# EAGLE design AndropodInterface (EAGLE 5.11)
AVAILABLE_QUANTITY: 27023; CREATE_DATE: 28.12.10; DATASHEET: http://www.farnell.com/cad/44942.pdf; DISTRIBUTOR: farnell.com; EDIT_DATE: 22.09.11; MANUFACTURER: MOLEX; MAUFACTURER: AVAGO; MINIMUM_QUANTITY: 1; ORDER_NO: 1568026; PARTS_PER_PACKAGE: 1; PART_NO: 47346-0001; PRICE: 1.21; PRICES: 1-0:1.21|25-0:1|50-0:0.834|100-0:0.725|500--1:0.629|; QUANTITY_MULTIPLIER: 1; TITLE: Andropod Interface
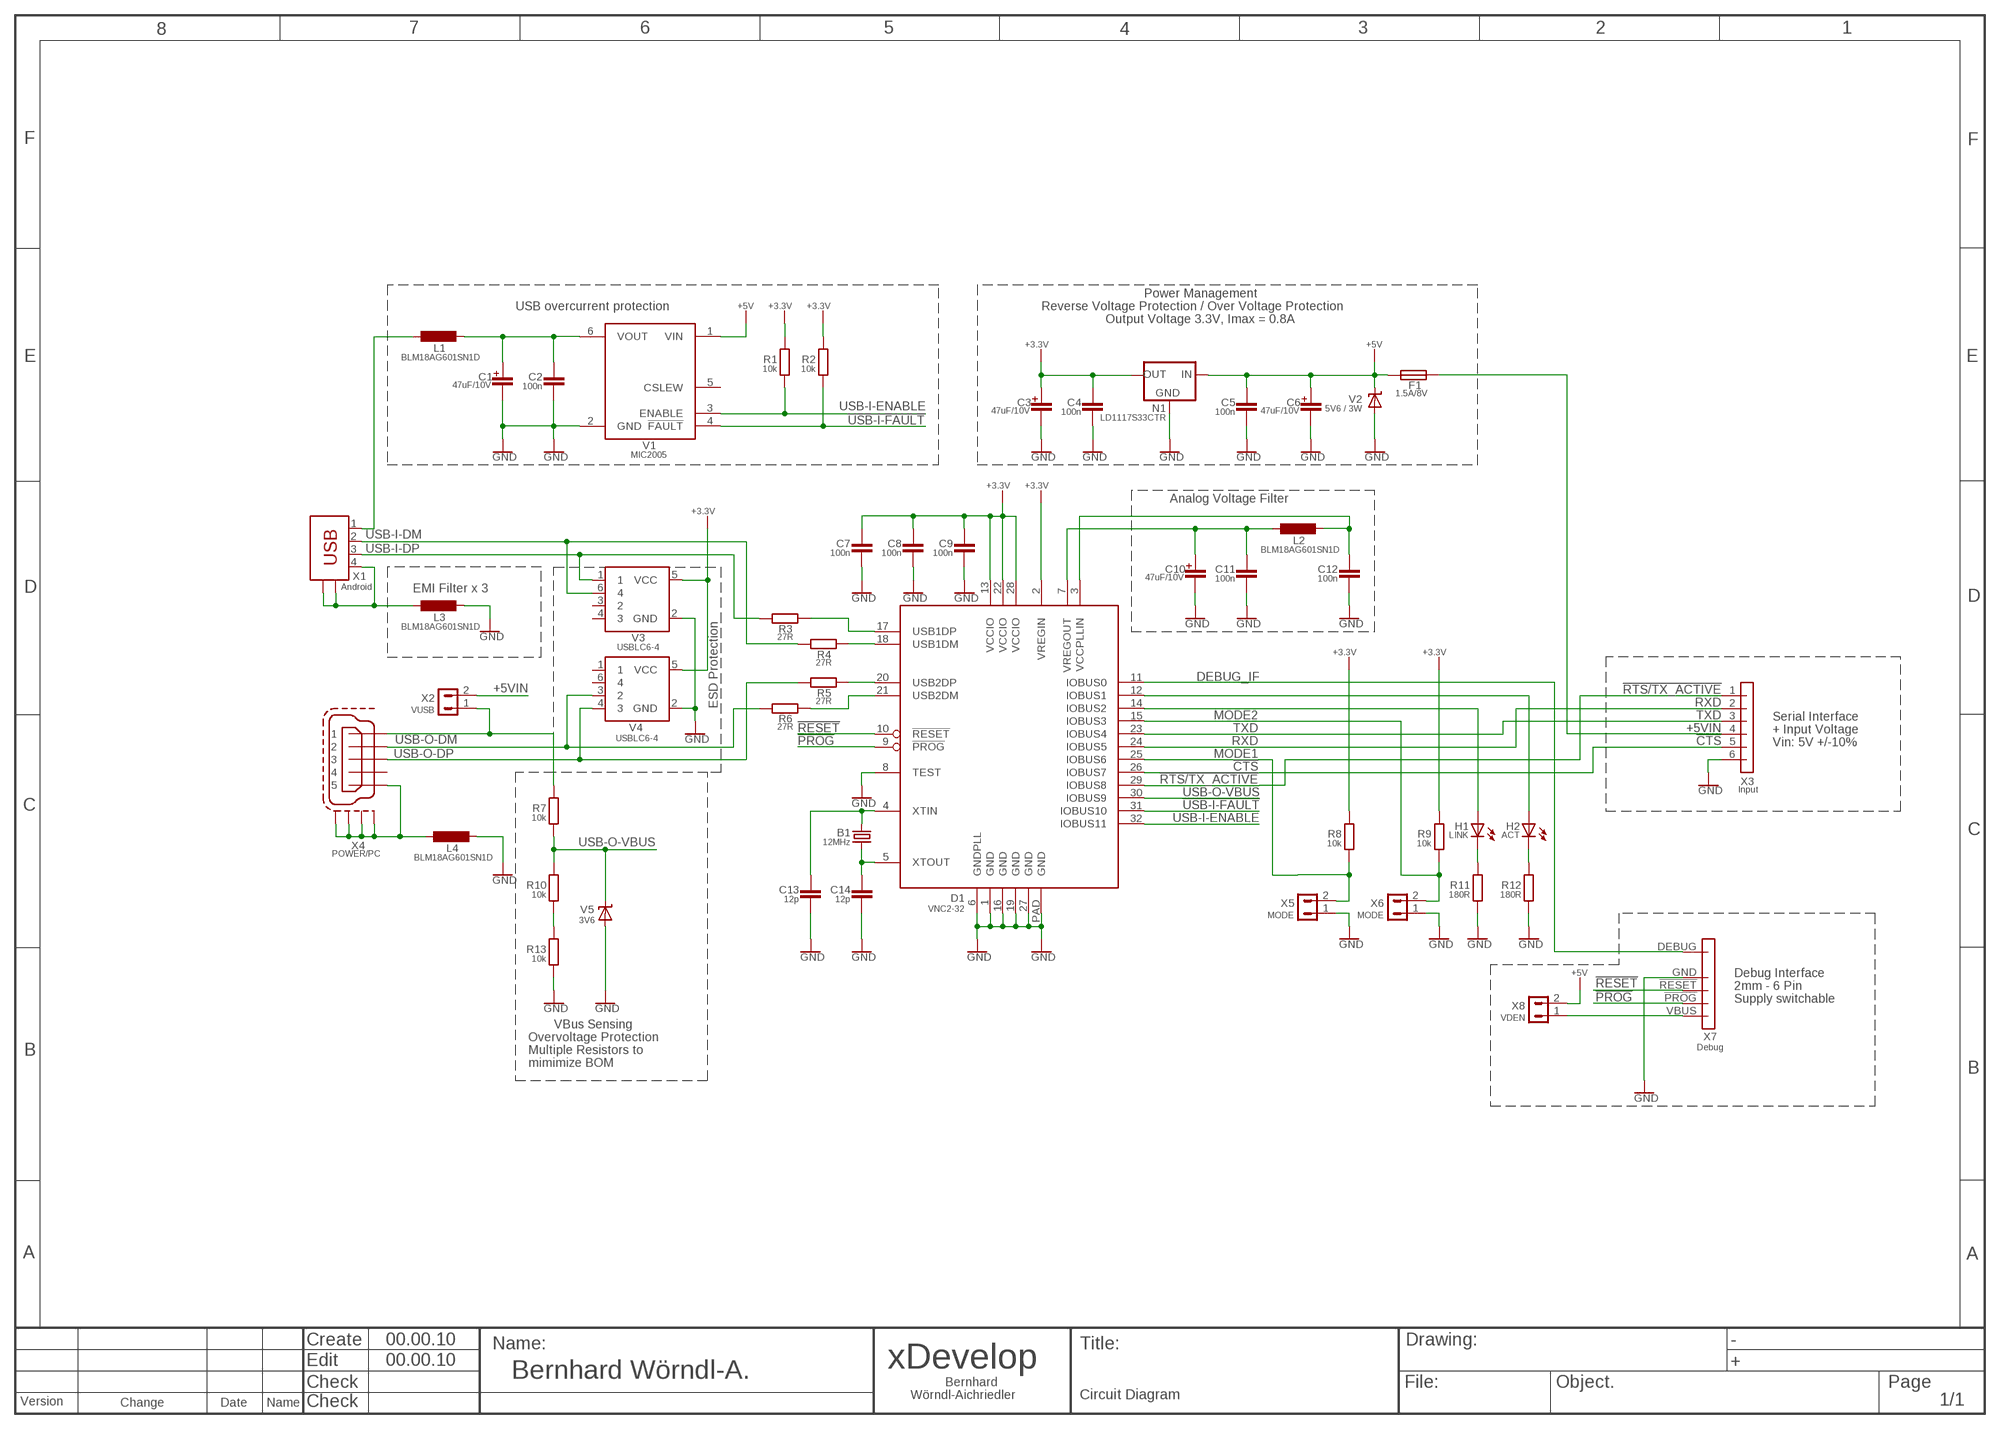
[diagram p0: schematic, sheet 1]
U$3 (XDEVELOP-A3): CREATE_DATE: 00.00.10; EDIT_DATE: 00.00.10; SUBTITLE: Circuit Diagram; USERNAME: Bernhard Wörndl-A.

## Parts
B1  12MHz  CRYSTAL5X3.2  [CRYSTAL-3.2X5.0MM]
C1  47uF/10V  CPOL-EUB/3528-21R  [B/3528-21R]
C2  100n  C-EUC0603  [C0603]
C3  47uF/10V  CPOL-EUB/3528-21R  [B/3528-21R]
C4  100n  C-EUC0603  [C0603]
C5  100n  C-EUC0603  [C0603]
C6  47uF/10V  CPOL-EUB/3528-21R  [B/3528-21R]
C7  100n  C-EUC0603  [C0603]
C8  100n  C-EUC0603  [C0603]
C9  100n  C-EUC0603  [C0603]
C10  47uF/10V  CPOL-EUB/3528-21R  [B/3528-21R]
C11  100n  C-EUC0603  [C0603]
C12  100n  C-EUC0603  [C0603]
C13  12p  C-EUC0603  [C0603]
C14  12p  C-EUC0603  [C0603]
D1  VNC2-32  [QFN32]
F1  1.5A/8V  POLYFUSE-1206  [F1206]
H1  LINK  LEDCHIP-LED0603  [CHIP-LED0603]
H2  ACT  LEDCHIP-LED0603  [CHIP-LED0603]
L1  BLM18AG601SN1D  L-EUL0805  [R0805]
L2  BLM18AG601SN1D  L-EUL0805  [R0805]
L3  BLM18AG601SN1D  L-EUL0805  [R0805]
L4  BLM18AG601SN1D  L-EUL0805  [R0805]
N1  LD1117S33CTR  LD1117-33CTR-S  [SOT223]
R1  10k  R-EU_R0603  [R0603]
R2  10k  R-EU_R0603  [R0603]
R3  27R  R-EU_R0603  [R0603]
R4  27R  R-EU_R0603  [R0603]
R5  27R  R-EU_R0603  [R0603]
R6  27R  R-EU_R0603  [R0603]
R7  10k  R-EU_R0603  [R0603]
R8  10k  R-EU_R0603  [R0603]
R9  10k  R-EU_R0603  [R0603]
R10  10k  R-EU_R0603  [R0603]
R11  180R  R-EU_R0603  [R0603]
R12  180R  R-EU_R0603  [R0603]
R13  10k  R-EU_R0603  [R0603]
V1  MIC2005  [SOT23-6L]
V2  5V6 / 3W  ZENER-DIODE-SMA  [SMA]
V3  USBLC6-4  [SOT23-6L]
V4  USBLC6-4  [SOT23-6L]
V5  3V6  ZENER-DIODE-SOT23-K3A1  [SOT23]
X1  Android  USB-A  [USB]
X2  VUSB  M02  [02P]
X3  Input  SIL6-R  [SIL6]
X4  POWER/PC  MICRO-USB  [MOLEX-47364-0001]
X5  MODE  M02  [02P]
X6  MODE  M02  [02P]
X7  Debug  VNC2-DEBUG  [VNC2-DEBUG]
X8  VDEN  M02  [02P]

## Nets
!CTS: D1.26(IOBUS7) X3.5
!PROG: D1.9(!PROG) X7.!PROG
!RESET: D1.10(!RESET) X7.!RESET
!RTS/TX_ACTIVE: D1.29(IOBUS8) X3.1
!USB-I-FAULT: D1.31(IOBUS10) R2.1 V1.4(!FAULT)
+3.3V: C3.+ C4.1 C7.1 C8.1 C9.1 D1.2(VREGIN) D1.13(VCCIO) D1.22(VCCIO) D1.28(VCCIO) N1.2(OUT) R1.2 R2.2 R8.2 R9.2 V3.5(VCC) V4.5(VCC)
+5V: C5.1 C6.+ F1.1 N1.3(IN) V1.1(VIN) V2.C X8.2
+5VIN: F1.2 X2.2 X3.4
DEBUG_IF: D1.11(IOBUS0) X7.DEBUG
GND: C1.- C2.2 C3.- C4.2 C5.2 C6.- C7.2 C8.2 C9.2 C10.- C11.2 C12.2 C13.2 C14.2 D1.1(GND) D1.6(GNDPLL) D1.8(TEST) D1.16(GND) D1.19(GND) D1.27(GND) D1.PAD(GND) L3.2 L4.2 N1.1(GND) R11.1 R12.1 R13.1 V1.2(GND) V2.A V3.2(GND) V4.2(GND) V5.3(A) X3.6 X5.1 X6.1 X7.GND
MODE1: D1.25(IOBUS6) R8.1 X5.2
MODE2: D1.15(IOBUS3) R9.1 X6.2
N$1: L4.1 X4.5 X4.GND1 X4.GND2 X4.GND3 X4.GND4
N$2: L3.1 X1.4 X1.SHIELD1(GND2) X1.SHIELD2(GND1)
N$4: R7.2 X2.1 X4.1
N$5: L1.1 X1.1
N$7: C1.+ C2.1 L1.2 V1.6(VOUT)
N$8: D1.18(USB1DM) R4.2
N$9: D1.17(USB1DP) R3.2
N$10: D1.21(USB2DM) R6.2
N$11: D1.20(USB2DP) R5.2
N$12: B1.1 C14.1 D1.5(XTOUT)
N$13: B1.3 C13.1 D1.4(XTIN)
N$14: C10.+ C11.1 D1.7(VREGOUT) L2.1
N$16: R10.1 R13.2
N$17: X7.VBUS X8.1
N$18: H1.C R11.2
N$19: H2.C R12.2
N$20: D1.14(IOBUS2) H1.A
N$21: D1.12(IOBUS1) H2.A
RXD: D1.24(IOBUS5) X3.2
TXD: D1.23(IOBUS4) X3.3
USB-I-DM: R4.1 V3.6 X1.2
USB-I-DP: R3.1 V3.1 X1.3
USB-I-ENABLE: D1.32(IOBUS11) R1.1 V1.3(ENABLE)
USB-O-DM: R6.1 V4.3 X4.2
USB-O-DP: R5.1 V4.4 X4.3
USB-O-VBUS: D1.30(IOBUS9) R7.1 R10.2 V5.1(C)
VCCPLLIN: C12.1 D1.3(VCCPLLIN) L2.2
Unconnected: V1.5(CSLEW) V3.3 V3.4 V4.1 V4.6 X4.4

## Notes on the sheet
- Power Management
- USB overcurrent protection | Reverse Voltage Protection / Over Voltage Protection
- Output Voltage 3.3V, Imax = 0.8A
- Analog Voltage Filter
- EMI Filter x 3
- ESD Protection
- Serial Interface
- + Input Voltage
- Vin: 5V +/-10%
- Debug Interface
- 2mm - 6 Pin
- Supply switchable
- VBus Sensing
- Overvoltage Protection
- Multiple Resistors to
- mimimize BOM

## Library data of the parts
B1 = Basic:CRYSTAL: CRYSTAL
C1 C3 C6 C10 = Basic:CPOL-EU: POLARIZED CAPACITOR, European symbol
C2 C4 C5 C7-C9 C11-C14 = Basic:C-EU: CAPACITOR, European symbol
D1 = Androdpod:VNC2-32; DISTRIBUTOR: digikey.at; MANUFACTURER: FTDI; ORDER_NO: 768-1050-1-ND; PART_NO: VNC2-32Q1B
F1 = Androdpod:POLYFUSE
H1 H2 = Basic:LED: LED
L1-L4 = Basic:L-EU: INDUCTOR, European symbol
N1 = Androdpod:LD1117; DISTRIBUTOR: farnell.com; MANUFACTURER: STMICROELECTRONICS; ORDER_NO: 1467780; PART_NO: LD1117S50CTR
R1-R13 = Basic:R-EU_: RESISTOR, European symbol
V1 = Androdpod:MIC2005; DISTRIBUTOR: farnell.com; MANUFACTURER: MICREL SEMICONDUCTOR; ORDER_NO: 1663121; PART_NO: MIC2005-0.5YM6 TR
V2 V5 = Basic:ZENER-DIODE
V3 V4 = Androdpod:USBLC6-4; DISTRIBUTOR: farnell.com; MANUFACTURER: STMICROELECTRONICS; ORDER_NO: 1295311; PART_NO: USBLC6-4SC6
X1 = Androdpod:USB-A: AMP connector; DISTRIBUTOR: farnell.com; MANUFACTURER: TYCO; ORDER_NO: 1654064; PART_NO: 1734366-1
X2 X5 X6 X8 = Androdpod:M02: AMP QUICK CONNECTOR
X3 = Androdpod:SIL6-R
X4 = Androdpod:MICRO-USB: MICRO USB B, BOTTOM MOUNT; DISTRIBUTOR: farnell.com; MANUFACTURER: MOLEX; ORDER_NO: 1568026; PART_NO: 47346-0001
X7 = Androdpod:VNC2-DEBUG

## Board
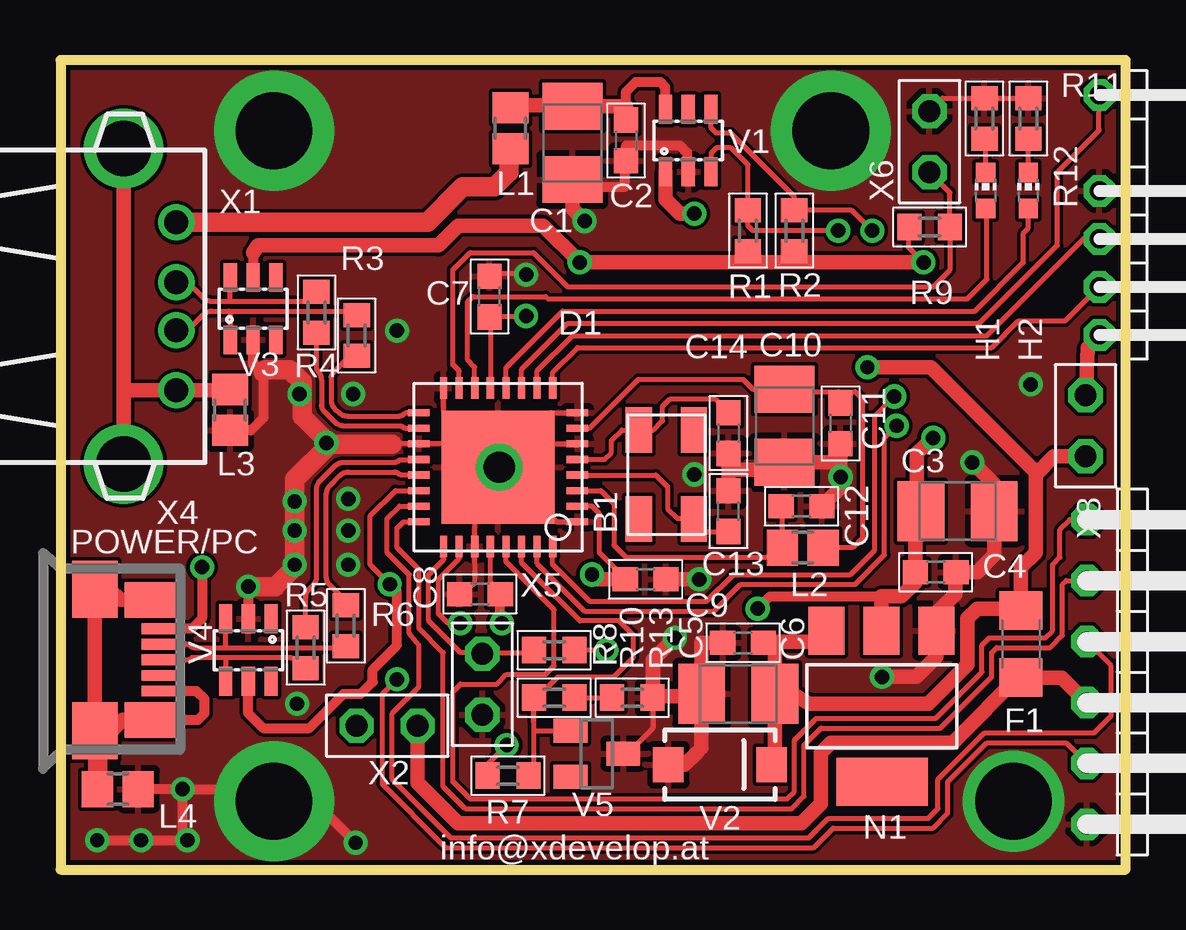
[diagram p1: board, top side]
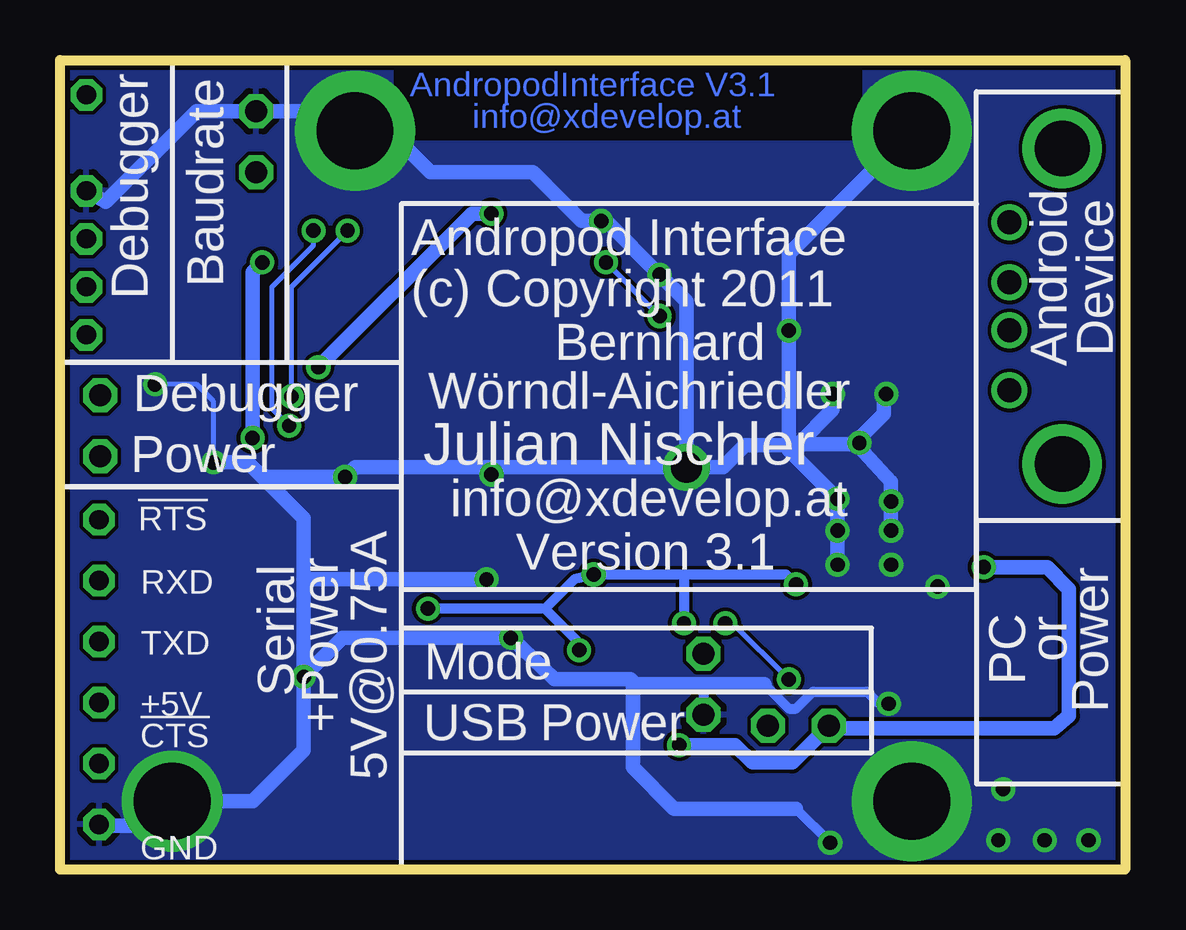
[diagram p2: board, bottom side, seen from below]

Size 44.43 x 33.73 mm. Coordinates in mm from the lower left corner, seen from the top.
Outline: 0.03,0 44.43,0 44.43,33.73 0.03,33.73 0.03,0
Copper layers (1*16): Top 0.035mm / dielectric 1.5mm / Bottom 0.035mm
Design rules "2layer *": minimum track width 6mil, minimum drill 23mil, track to track 6mil, track to pad 6mil, pad to pad 6mil, via to via 6mil, smd to smd 6mil, copper to edge 8mil, drill to drill 8mil, minimum pad ring 10mil, minimum via ring 8mil, stop-mask expansion 4mil, vias tented up to drill 0mil, thermal gap 10mil
tRestrict: area -7.5,0.6 to -4.3,4.2
bRestrict: area 11,30.4 to 30.5,33.7

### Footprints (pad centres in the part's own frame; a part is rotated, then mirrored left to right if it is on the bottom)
CRYSTAL-3.2X5.0MM = smd 1.9 x 1.1: 1 1.85,1.15; 2 -1.85,1.15; 3 -1.85,-1.15; 4 1.85,-1.15
B/3528-21R = smd 1.95 x 2.5: + 1.525,0; - -1.525,0
C0603 = smd 1.05 x 1: 1 -0.85,0; 2 0.85,0
QFN32 = smd 0.3 x 0.9: 1 -2.275,-3.3; 2 -1.625,-3.3; 3 -0.975,-3.3; 4 -0.325,-3.3; 5 0.325,-3.3; 6 0.975,-3.3; 7 1.625,-3.3; 8 2.275,-3.3; 17 2.275,3.3; 18 1.625,3.3; 19 0.975,3.3; 20 0.325,3.3; 21 -0.325,3.3; 22 -0.975,3.3; 23 -1.625,3.3; 24 -2.275,3.3 | smd 0.9 x 0.3: 9 3.3,-2.275; 10 3.3,-1.625; 11 3.3,-0.975; 12 3.3,-0.325; 13 3.3,0.325; 14 3.3,0.975; 15 3.3,1.625; 16 3.3,2.275; 25 -3.3,2.275; 26 -3.3,1.625; 27 -3.3,0.975; 28 -3.3,0.325; 29 -3.3,-0.325; 30 -3.3,-0.975; 31 -3.3,-1.625; 32 -3.3,-2.275 | smd 4.7 x 4.7: PAD 0,0
F1206 = smd 1.6 x 1.8: 1 -1.4,0; 2 1.4,0
CHIP-LED0603 = smd 0.8 x 0.8: A 0,-0.75; C 0,0.75
R0805 = smd 1.3 x 1.5: 1 -0.85,0; 2 0.85,0
SOT223 = smd 1.499 x 2.007: 1 -2.261,-3.15; 2 0.025,-3.15; 3 2.311,-3.15 | smd 3.81 x 2.007: 4 0,3.15
R0603 = smd 1 x 1.1: 1 -0.85,0; 2 0.85,0
SOT23-6L = smd 0.55 x 1.2: 1 -0.95,-1.3; 2 0,-1.3; 3 0.95,-1.3; 4 0.95,1.3; 5 0,1.3; 6 -0.95,1.3
SMA = smd 1.27 x 1.47: A -2.15,0; C 2.15,0
SOT23 = smd 1 x 1.4: 1 -0.95,-1.1; 2 0.95,-1.1; 3 0,1.1
USB = drill 1 round: 1 -3.5,12.9; 2 -1,12.9; 3 1,12.9; 4 3.5,12.9 | drill 2.3 round: SHIELD1 -6.57,10.7; SHIELD2 6.57,10.7
02P = drill 0.914 octagon: 1 -1.27,0; 2 1.27,0
SIL6 = drill 0.8 octagon: 1 0,6.35; 2 0,3.81; 3 0,1.27; 4 0,-1.27; 5 0,-3.81; 6 0,-6.35
MOLEX-47364-0001 = smd 1.7 x 0.45: 1 2.8,1.3; 2 2.8,0.65; 3 2.8,0; 4 2.8,-0.65; 5 2.8,-1.3 | smd 1.9 x 2.375: GND1 0,2.95; GND4 0,-2.95 | smd 2.1 x 1.475: GND2 2.3,2.5; GND3 2.3,-2.5
VNC2-DEBUG = drill 0.8 octagon: !PROG -1,-3; !RESET -1,-1; DEBUG -1,5; GND -1,1; VBUS -1,-5

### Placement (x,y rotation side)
B1  25.28,16.46 90 top
C1  21.36,30.28 90 top
C2  23.6,30.38 270 top
C3  37.42,14.94 180 top
C4  36.5,12.4 0 top
C5  28.48,9.45 180 top
C6  28.27,7.32 0 top
C7  17.91,23.88 90 top
C8  17.5,11.48 180 top
C9  24.41,12.09 0 top
C10  30.2,18.49 90 top
C11  32.54,18.59 270 top
C12  30.91,15.14 0 top
C13  27.87,14.94 90 top
C14  27.87,18.19 270 top
D1  18.26,16.76 90 top
DRILEGEND  [DRILEGEND]  not placed on the board
F1  40.06,9.4 270 top
H1  38.58,28.3 0 top
H2  40.36,28.3 0 top
L1  18.77,30.89 90 top
L2  30.96,13.41 180 top
L3  7.09,19.15 270 top
L4  2.42,3.35 0 top
MEASURE  [MEASURE]  0.03,0.2 0 top
N1  34.27,6.81 180 top
R1  28.68,26.62 270 top
R2  30.61,26.62 270 top
R3  12.37,22.25 270 top
R4  10.7,23.22 270 top
R5  10.24,9.25 90 top
R6  11.91,10.16 90 top
R7  18.67,3.91 180 top
R8  20.6,9.14 0 top
R9  36.25,26.77 180 top
R10  20.6,7.16 180 top
R11  38.53,31.29 270 top
R12  40.36,31.29 270 top
R13  23.85,7.16 180 top
V1  26.19,30.38 0 top
V2  27.51,4.37 0 top
V3  8.05,23.37 0 top
V4  7.85,9.14 180 top
V5  22.38,4.83 270 top
X1  -8.05,23.47 270 top
X2  13.64,5.99 0 top
X3  42.8,8.23 0 top
X4  1.45,8.74 0 top
X5  17.6,7.72 90 top
X6  36.25,30.33 270 top
X7  44.33,27.28 0 top
X8  42.75,18.49 270 top

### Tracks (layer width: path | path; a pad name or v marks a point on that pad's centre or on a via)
!CTS  (via drill 0.6)
  Top 0.203: D1.26 16.64,12.95 15.78,12.09 15.78,10.67 16.18,10.26 v16.69,10.26 | v14.05,7.93 13.44,7.32 13.44,3.56 15.98,1.02 16.08,0.91 31.42,0.91 32.23,1.73 36.4,1.73 37.01,2.34 37.01,3.66 38.64,5.28 41.94,5.28 X3.5
  Bottom 0.203: v16.69,10.26 16.39,10.26 v14.05,7.93
!PROG
  Top 0.203: D1.9 20.54,20.72 21.57,21.74 38.84,21.74 39.96,22.86 41.9,22.86 X7.!PROG
!RESET
  Top 0.203: D1.10 19.89,20.78 21.36,22.25 38.64,22.25 42.7,26.31 43.29,26.31 X7.!RESET
!RTS/TX_ACTIVE
  Top 0.203: X3.1 42.09,14.58 41.68,14.17 41.68,13.01 41.38,12.7 41.38,9.96 41.07,9.65 38.74,9.65 38.43,9.35 38.43,8.23 36.5,6.3 31.52,6.3 30.61,5.39 30.61,3.25 30.3,2.95 17.1,2.95 16.39,3.66 16.39,7.42 16.69,7.72 18.21,7.72 18.62,8.13 20.25,8.13 20.6,8.48 20.6,10.82 18.59,12.83 D1.29
!USB-I-FAULT  (via drill 0.6)
  Top 0.203: V1.4 27.14,30.9 27.36,30.68 27.97,30.68 30.61,28.04 R2.1 33.01,27.47 v33.86,26.62 | D1.31 19.89,12.75 21.87,10.77 27.26,10.77 28.37,11.89 33.15,11.89 34.37,13.11 34.37,17.98 v34.88,18.49
  Bottom 0.203: v34.88,18.49 35.59,19.2 35.59,24.28 33.86,26.01 v33.86,26.62
+3.3V  (via drill 0.6, 0.6 pad 0.61)
  Top 0.203: D1.28 17.94,12 C8.1 | D1.2 22.18,15.14 22.48,14.83 22.48,13.21 23.6,12.09 23.6,12.16 C9.1 | D1.22 13.99,15.79 12.93,14.73 12.93,12.7 v13.74,11.89 | D1.13 17.94,23 C7.1 19.4,23.03 v19.43,23.06 | R9.2 35.38,26.76 35.38,25.91 v35.99,25.3 | R1.2 28.68,25.5 28.88,25.3 | R2.2 30.61,25.4 30.51,25.3 | v22.79,9.14 R8.2
  Top 0.406: 34.24,11.39 29.6,11.39 v29.09,10.87 | C8.1 18.35,10.4 v18.42,10.26 | V4.5 7.85,6.5 8.46,5.89 10.39,5.89 11.81,7.32 12.52,7.32 13.03,7.82 13.03,8.33 14.05,9.35 14.05,11.58 v13.74,11.89 | 8.05,25.71 V3.5
  Top 0.61: N1.2 34.24,11.39 34.33,11.38 35.08,11.38 35.65,11.95 C4.1 35.65,14.59 arc-45 35.73,14.77 | 35.73,14.77 C3.+ | 35.73,14.77 35.73,17.34 v36.4,17.98 | C9.1 22.38,12.09 v22.18,12.29 | R1.2 28.64,25.81 | v35.99,25.3 30.51,25.3 28.88,25.3 v21.67,25.3 20.14,26.82 16.59,26.82 15.78,26.01 8.26,26.01 8.05,25.71
  Bottom 0.203: v21.67,25.3 v19.43,23.06
  Bottom 0.406: 24.21,10.87 v29.09,10.87 | 24.21,10.87 22.99,12.09 v22.18,12.29 18.42,12.29 | 18.42,12.29 v18.42,10.26 | v13.74,11.89 14.15,12.29 18.42,12.29 | v22.79,9.14 22.58,9.25 24.21,10.87
  Bottom 0.61: v36.4,17.98 36.4,24.89 v35.99,25.3
+5V  (via drill 0.6)
  Top 0.61: 29.8,4.06 V2.C 29.59,4.37 29.8,4.57 29.8,7.21 C6.+ | C6.+ 30.71,7.21 31.22,6.91 36.2,6.91 37.82,8.53 37.82,10.47 38.23,10.87 39.83,10.87 F1.1 | F1.1 39.85,11.28 | 40.67,14.53 40.67,13.21 40.06,12.6 F1.1 | 40.67,14.53 40.67,16.46 | 40.67,16.46 40.67,16.56 36.3,20.93 v33.66,20.93 | 40.67,16.46 40.67,16.66 40.67,16.46 | 40.67,16.46 41.43,17.22 X8.2 | 40.67,14.53 40.67,16.46 | V1.1 25.24,27.93 25.83,27.33 v26.44,27.33 | C6.+ 29.8,9.49 | 29.8,9.49 C5.1 | 29.8,9.49 30.24,9.49 31.93,9.5 N1.3
  Bottom 0.61: v33.66,20.93 27.26,27.33 v26.44,27.33
+5VIN
  Top 0.61: X2.2 14.91,3.61 16.59,1.93 30.91,1.93 31.73,2.74 31.73,4.88 32.13,5.28 37.21,5.28 40.06,8.13 F1.2 41.76,8 X3.4
DEBUG_IF
  Top 0.203: D1.11 19.24,20.84 21.16,22.76 38.33,22.76 41.58,26.01 41.58,29.06 43.31,30.79 43.31,30.84 X7.DEBUG
GND  (via drill 0.6, 0.6 pad 0.61, 1.3, 3.2 pad 3.3, 3.2 pad 5)
  Top 0.203: D1.6 20.49,17.74 20.45,17.78 | 20.45,18.9 20.45,19 20.49,19.04 D1.8 | 20.45,17.78 20.45,18.9 | 16.08,17.68 16.02,17.74 D1.19 13.85,17.74 13.85,17.73 | 16.08,17.68 16.08,19 | 16.08,19 20.35,19 20.45,18.9 | 16.08,16.76 16.08,14.63 17.3,14.63 | 16.08,16.76 16.08,17.68 | 17.3,14.63 20.45,14.63 20.45,14.73 | 20.45,16.76 20.45,14.73 | 20.45,16.76 20.45,17.78 | D1.1 20.69,14.49 20.45,14.73 | 17.3,14.63 17.29,14.62 D1.27 17.29,11.91 C8.2 | D1.16 15.99,19.09 16.08,19 | V5.3 23.65,4.83 24.72,5.89 24.72,7.21 24.72,7.15 R13.1 | R12.1 R11.1 36.79,32.14 X6.1 | C7.2 17.91,24.79 17.95,24.83 19.37,24.83 v19.43,24.79 | 16.08,16.76 v18.32,16.76 20.45,16.76
  Top 0.406: V1.2 26.14,29.13 26.14,29.87 25.83,30.18 23.6,30.18 C2.2 23.53,28.45 21.36,28.45 C1.- | V4.2 v7.85,11.79 7.85,11.89 | L3.2 7.97,18.3 8.46,18.8 8.46,20.73 8.46,20.83 8.05,21.03 V3.2 | v5.11,3.35 L4.2 | v5.11,3.35 5.11,1.42 v5.31,1.22 v3.38,1.22 v1.55,1.22 | v5.11,3.35 8.41,3.35 v8.92,2.85 10.59,2.85 v12.32,1.12
  Top 0.61: 24.72,7.21 24.72,7.15 | 24.72,7.21 25.83,7.21 26.55,7.32 26.54,7.32 arc-45 26.72,7.24 C6.- | C3.- arc-45 C3.- | 32.54,16.87 v32.54,16.36 32.54,15.91 C12.2 | 32.54,16.87 C11.2 | 32.54,16.87 32.44,16.97 C10.- 29.9,16.66 27.87,16.66 | 27.87,16.66 C13.2 | 27.87,16.66 C14.2 | C3.- 38.94,16.05 v38.03,16.97 | v34.27,8.03 35.69,8.03 36.53,8.86 N1.1 36.53,10.69 37.31,11.48 37.31,12.36 C4.2 38.23,12.4 38.94,13.11 C3.- | v25.63,9.65 24.72,8.74 24.72,7.21 | 24.72,7.21 24.72,7.15 | 24.72,7.21 24.72,7.15 | v26.65,12.09 C9.2 | v21.87,27.03 21.36,27.53 C1.- | C5.2 26.75,9.45 C6.- 26.75,7.21 C6.- | V2.A 26.04,4.37 26.55,4.88 26.75,5.08 C6.- | v9.78,14.12 v9.78,12.7
  Top 0.813: 13.85,17.73 11.25,17.73 | 11.25,17.73 9.78,16.26 v9.78,14.12 v9.78,12.7 9.78,12.6 8.97,11.79 v7.85,11.79 | 11.25,17.73 10.09,18.9 10.09,20.32 9.58,20.83 8.56,20.83 8.46,20.73
  Bottom 0.203: 14.05,17.94 13.85,17.74 13.89,17.74 13.95,17.68 | v40.46,20.22 38.74,20.22 38.03,19.51 v38.03,16.97
  Bottom 0.406: v9.88,6.91 10.29,6.91 10.8,7.42 13.03,7.42 13.74,6.71 14.05,6.71 15.06,7.72 | v12.32,1.12 13.74,2.54 | 17.6,7.72 X5.1 | v26.44,16.46 26.44,16.66 26.34,16.76 | v18.32,16.76 D1.PAD
  Bottom 0.61: v39.75,2.85 40.67,1.93 | 40.67,1.93 40.77,1.83 | 40.77,1.83 41.02,1.58 | v39.75,2.85 36.4,2.85 34.27,4.98 v34.27,8.03 | v34.27,8.03 32.64,9.65 25.73,9.65 v25.63,9.65 23.8,7.93 20.65,7.93 20.55,7.82 | v26.65,12.09 31.73,12.09 34.27,12.09 | v34.27,8.03 34.27,12.09 | v38.03,16.97 36.6,16.97 35.99,16.36 | 35.99,16.36 34.27,14.63 34.27,12.09 | 34.27,12.09 34.27,11.79 34.27,12.09 | 35.99,16.36 v32.54,16.36 32.13,16.76 26.34,16.76 v18.32,16.76 | X7.GND 42.51,27.82 38.74,31.6 X6.1 32.95,31.6 v32.13,30.79 31.93,30.58 30.51,30.58 28.98,29.06 24.72,29.06 22.68,27.03 v21.87,27.03 21.67,27.03 v19.43,24.79 18.32,23.67 v18.32,16.76 | v18.32,16.76 D1.PAD 16.79,16.76 15.88,17.68 14.05,17.68 | 14.05,17.68 13.95,17.68 | v39.75,2.85 40.67,1.93 | 40.67,1.93 40.77,1.83 | 40.77,1.83 42.8,1.83 | v12.22,19.81 12.22,19.15 13.64,17.73 11.15,17.73 | 11.15,17.73 v11.1,17.78 | 11.15,17.63 11.15,17.73 | 11.15,17.63 9.78,16.15 v9.78,15.34 v9.78,14.12 | 14.05,17.68 14.05,17.48 v12.02,15.44 v12.02,14.12 v12.02,12.7 | 11.15,17.63 11.15,17.93 10.09,19 10.09,19.71 v9.98,19.81 | 14.05,17.94 v14.05,22.45 14.05,25.65 v8.92,30.79 | 13.74,2.54 18.82,2.54 20.55,4.27 20.55,5.08 20.55,6.81 20.55,7.82 | 15.06,7.72 17.6,7.72 18.72,7.72 20.45,7.72 20.55,7.82
  pour Top: 0.03,0 44.43,0 44.53,33.73 0.03,33.73
  pour Bottom: 0.03,0.1 44.43,0 44.53,33.73 0.03,33.73
MODE1
  Top 0.203: D1.25 15.99,12.91 15.37,12.29 15.37,10.36 16.39,9.35 16.69,9.04 17.6,9.04 | 17.6,9.04 19.5,9.04 R8.1 | X5.2 17.6,9.04
MODE2
  Top 0.203: D1.15 16.64,20.78 16.39,21.03 16.39,24.99 17.1,25.71 19.74,25.71 21.16,24.28 36.4,24.28 37.11,24.99 37.11,26.76 R9.1 37.1,28.21 X6.2
N$1
  Top 0.406: X4.5 5.7,7.44 6.02,7.11 6.02,6.5 5.76,6.24 X4.GND3
  Top 0.61: X4.GND2 2.51,11.24 2.06,11.68 X4.GND1 | X4.GND1 | X4.GND3 2.61,6.24 2.16,5.79 X4.GND4 | X4.GND4 | X4.GND4 X4.GND1
  Top 0.813: L4.1 1.57,5.67 X4.GND4
N$2
  Top 0.406: L3.1 7.09,19.97
  Top 0.61: X1.SHIELD2 2.65,20.02 | 2.65,20.02 X1.SHIELD1 | 2.65,20.02 2.7,19.97 X1.4 7.06,19.97 L3.1
N$4  (via drill 0.6, 0.6 pad 0.61)
  Top 0.203: v18.62,5.18 17.71,4.27 17.71,4.03 R7.2
  Top 0.406: X4.1 5.49,10.04 5.92,10.47 v5.92,12.6
  Bottom 0.406: 12.37,5.89 X2.1
  Bottom 0.61: v18.62,5.18 16.28,5.18 15.57,4.47 13.9,4.47 X2.1 | v5.92,12.6 3.28,12.6 2.36,11.68 2.36,6.4 2.97,5.89 4.8,5.89 5.31,5.89 11.15,5.89 12.37,5.89
N$5
  Top 0.61: 18.72,29.91 arc-45 L1.1
  Top 0.813: 18.72,29.91 18.72,29.06 18.11,28.45 16.79,28.45 15.31,26.97 X1.1
N$7
  Top 0.406: C2.1 23.6,31.09 | V1.6 25.22,31.66 25.22,32.61 25.02,32.82 24.01,32.82 23.6,32.41 23.6,31.8
  Top 0.61: C2.1 23.6,31.8 C1.+ 21.31,31.85 18.99,31.85 arc45 18.81,31.78 L1.2
N$8
  Top 0.203: D1.18 14.39,18.39 arc-45 14.33,18.42 arc45 14.15,18.49 11.82,18.49 arc-45 11.46,18.64 11,19.1 arc-45 10.9,19.35 10.9,20.41 arc45 10.75,20.77 arc-45 10.7,20.91 R4.2
N$9
  Top 0.203: D1.17 14.49,19.04 arc45 14.33,18.97 arc-45 14.15,18.9 11.97,18.9 arc-45 11.61,19.05 11.45,19.21 arc-45 11.31,19.57 11.31,20.49 arc-45 11.4,20.72 11.88,21.2 R3.2
N$10
  Top 0.203: R6.2 11.88,11.21 11.25,11.84 arc-45 11.1,12.2 11.1,15.64 arc-45 11.25,16 11.66,16.41 arc-45 12.02,16.56 13.94,16.56 arc-45 14.12,16.49 arc45 14.19,16.46 14.94,16.46 D1.21
N$11
  Top 0.203: R5.2 10.24,11.32 arc-45 10.39,11.68 10.55,11.84 arc45 10.7,12.2 10.7,15.84 arc-45 10.84,16.2 11.46,16.82 arc-45 11.82,16.97 13.94,16.97 arc45 14.12,17.04 arc-45 14.19,17.07 14.94,17.07 D1.20
N$12
  Top 0.203: D1.5 22.7,17.09 22.99,17.38 22.99,17.88 23.42,18.31 B1.1 | B1.1 24.11,18.33 | C14.1 27.29,19.61 25.43,19.61 25.12,19.3 25.12,18.69 24.74,18.31 B1.1
N$13
  Top 0.203: C13.1 26.95,14.09 B1.3 26.4,14.63 25.73,14.63 25.33,15.04 25.33,15.95 24.84,16.44 D1.4
N$14
  Top 0.203: L2.1 33.05,13.41 33.45,13.82 33.45,19.61 33.15,19.91 32.44,19.91 | 32.44,19.91 30.31,19.91 C10.+ 28.88,20.02 28.48,20.42 24.11,20.42 22.07,18.39 D1.7 | C11.1 32.54,19.81 32.44,19.91
N$16
  Top 0.203: R10.1 R13.2
N$17
  Top 0.61: X8.1 42.85,21.74 X7.VBUS
N$18
  Top 0.203: H1.C 38.58,30.39 R11.2
N$19
  Top 0.203: H2.C R12.2
N$20
  Top 0.203: D1.14 17.29,20.94 16.99,21.23 16.99,23.67 17.2,23.88 20.25,23.88 20.35,23.77 37.82,23.77 38.64,24.59 38.64,27.64 38.58,27.58 H1.A
N$21
  Top 0.203: D1.12 18.59,20.9 20.96,23.27 38.13,23.27 40.16,25.3 40.16,26.52 40.36,26.72 H2.A
RXD
  Top 0.203: D1.24 14.31,14.49 14.05,14.22 14.05,13.41 14.96,12.5 14.96,10.06 15.98,9.04 15.98,3.45 16.89,2.54 30.51,2.54 31.02,3.05 31.02,5.18 31.73,5.89 36.71,5.89 38.84,8.03 38.84,9.04 39.04,9.25 41.28,9.25 41.79,9.75 41.79,11.89 41.94,12.04 X3.2
TXD
  Top 0.203: D1.23 14.15,15.14 13.64,14.63 13.64,13.21 14.56,12.29 14.56,9.86 14.96,9.35 14.96,7.62 13.85,6.5 13.85,3.76 16.28,1.32 31.22,1.32 32.03,2.13 36.2,2.13 36.6,2.54 36.6,3.76 38.53,5.69 43.11,5.69 43.82,6.4 43.82,8.48 X3.3
USB-I-DM
  Top 0.203: X1.2 5.12,24.47 arc-45 5.48,24.32 5.97,23.82 arc45 6.33,23.67 7.14,23.67 | 7.14,23.67 10.61,23.67 R4.1 | V3.6 7.1,23.74 7.14,23.67
USB-I-DP
  Top 0.203: X1.3 5.12,22.47 arc45 5.48,22.62 5.97,23.12 arc-45 6.33,23.27 7.04,23.27 | 7.04,23.27 12.21,23.27 R3.1 | V3.1 7.1,23.23 7.04,23.27
USB-I-ENABLE  (via drill 0.6)
  Top 0.203: V1.3 27.14,29.86 27.36,30.07 27.97,30.07 28.68,29.36 R1.1 28.68,26.82 28.88,26.62 v32.44,26.62 | D1.32 20.54,12.71 22.07,11.18 26.95,11.18 28.07,12.29 32.95,12.29 33.96,13.31 33.96,18.9 v34.77,19.71
  Bottom 0.203: v34.77,19.71 34.77,24.28 v32.44,26.62
USB-O-DM
  Top 0.203: X4.2 5.27,9.39 arc-45 5.45,9.31 arc45 5.61,9.25 6.83,9.25 | 6.83,9.25 11.41,9.25 11.61,9.45 11.48,9.39 R6.1 | V4.3 6.9,9.31 6.83,9.25
USB-O-DP
  Top 0.203: X4.3 5.31,8.74 arc45 5.49,8.81 arc-45 5.55,8.84 6.83,8.84 | 6.83,8.84 9.54,8.84 arc-45 9.78,8.74 9.77,8.74 R5.1 | V4.4 6.9,8.8 6.83,8.84
USB-O-VBUS
  Top 0.203: D1.30 19.24,12.79 19.43,12.6 19.74,12.29 21.67,10.36 23.29,10.36 23.9,9.75 23.9,8.84 23.09,8.03 20.75,8.03 19.74,7.01 19.74,6.16 R10.2 19.75,5.79 | 19.75,5.79 19.75,4.14 R7.1 | V5.1 19.77,5.78 19.75,5.79
VCCPLLIN
  Top 0.203: D1.3 22.54,15.79 23.09,15.24 23.09,13.51 23.6,13.01 29.4,13.01 L2.2 30.11,15.09 C12.1

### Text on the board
Bottom: AndropodInterface V3.1 | info@xdevelop.at
tPlace: info@xdevelop.at
bPlace: Baudrate | Debugger | Device | Android | Andropod Interface | (c) Copyright 2011 | Bernhard | Wörndl-Aichriedler | Debugger | Julian Nischler | Power | info@xdevelop.at | 5V@0.75A | !RTS | +Power | Power | Version 3.1 | Serial | RXD | or | PC | TXD | Mode | +5V | Power | USB | !CTS | GND
_tsilk: R11 | V1 | BAUD | L1 | X6 | X1 | C1 | C2 | R12 | Android | R3 | 27R | R1 | C7 | R2 | R9 | ACT | 100n | 10k | 10k | LINK | D1 | C14 | 10k | C10 | V3 | VNC2-32 | 12p | H1 | H2 | R4 | C11 | 27R | VDEN | L3 | 12MHz | C3 | X4 | B1 | X8 | POWER/PC | C13 | C12 | R5 | X5 | L2 | C4 | C8 | R13 | R6 | MODE | C9 | 27R | R8 | C5 | C6 | V4 | 27R | R10 | F1 | X2 | R7 | L4 | VUSB | V5 | V2 | info@xdevelop.at | N1
_bsilk: Baudrate | Debugger | Device | Android | Andropod Interface | (c) Copyright 2010 | Bernhard | Wörndl-Aichriedler | Debugger | Julian Nischler | Power | info@xdevelop.at | 5V@0.75A | !RTS | +Power | Power | Version 3.0 | Serial | RXD | or | PC | Mode | TXD | +5V | Power | USB | !CTS | GND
